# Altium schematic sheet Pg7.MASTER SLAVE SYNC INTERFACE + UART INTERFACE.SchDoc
size 431 x 279 mm; Date: Not shown in title block; ApprovedBy: Not shown in title block; CheckedBy: Not shown in title block; Author: Not shown in title block; CompanyName: Not shown in title block; Engineer: Not shown in title block; Organization: Not shown in title block; Address1: Not shown in title block; Address2: Not shown in title block; Address3: Not shown in title block; Address4: Not shown in title block; DocumentNumber: 7; Revision: Use project parameter SCH_Rev; SheetNumber: 7; SheetTotal: 8; PageSetup: Record=PageOptions|CenterHorizontal=True|CenterVertical=True|PrintScale=1.00|XCorrection=1.00|YCorrection=1.00|PrintKind=0|BorderSize=5000000|LeftOffset=0|BottomOffset=0|Orientation=2|PaperLength=1000|PaperWidth=1000|Scale=100|PaperSource=15|PrintQuality=600|MediaType=1|DitherType=10|PaperKind=Letter|PrintScaleMode=1
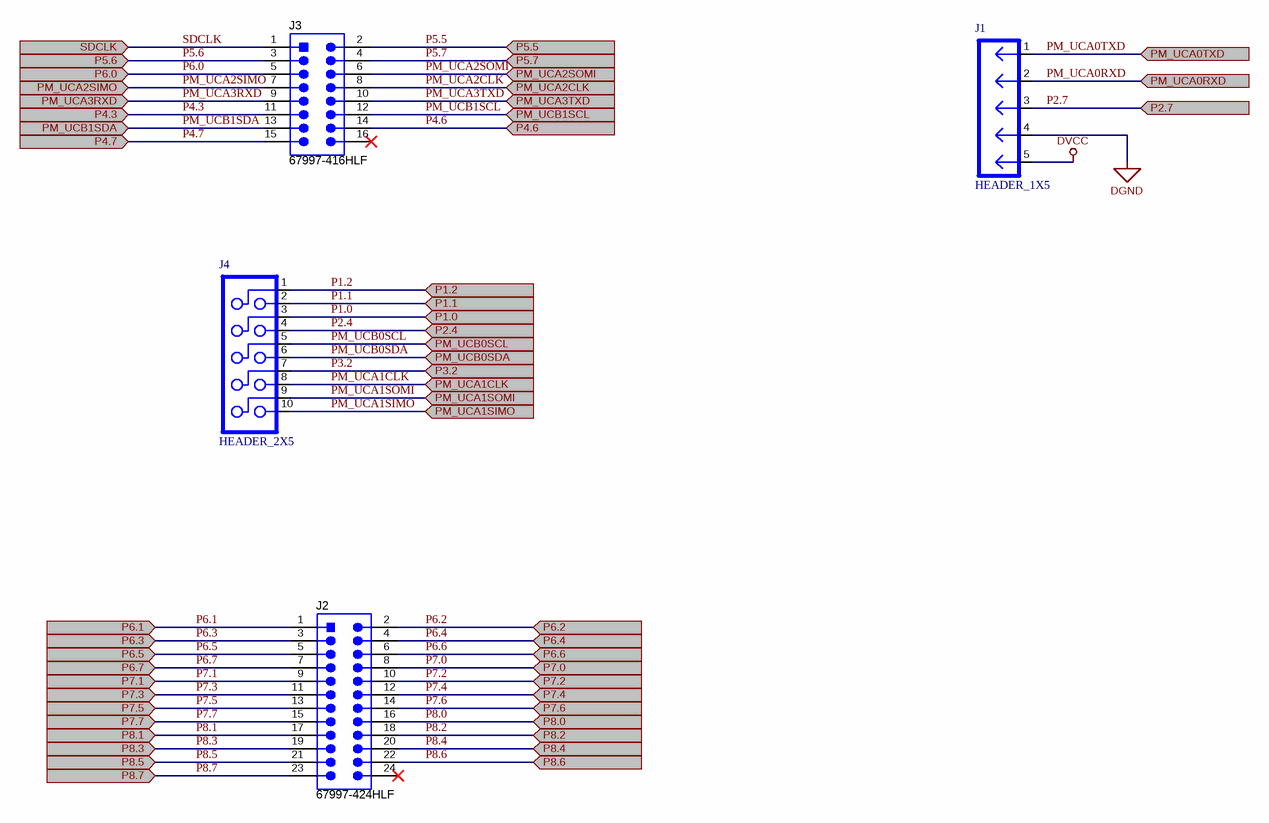
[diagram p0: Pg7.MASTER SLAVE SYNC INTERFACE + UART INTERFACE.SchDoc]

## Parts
J1  HEADER_1X5  [HEADER_5P]
J2  67997-424HLF  [TSW-112-07-G-D]
J3  67997-416HLF  [TSW-108-07-G-D]
J4  HEADER_2X5  [HDR2X5]

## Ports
P1.0, P1.1, P1.2, P2.4, P2.7, P3.2, P4.3, P4.6, P4.7, P5.5, P5.6, P5.7, P6.0, P6.1, P6.2, P6.3, P6.4, P6.5, P6.6, P6.7, P7.0, P7.1, P7.2, P7.3, P7.4, P7.5, P7.6, P7.7, P8.0, P8.1, P8.2, P8.3, P8.4, P8.5, P8.6, P8.7, PM_UCA0RXD, PM_UCA0TXD, PM_UCA1CLK, PM_UCA1SIMO, PM_UCA1SOMI, PM_UCA2CLK, PM_UCA2SIMO, PM_UCA2SOMI, PM_UCA3RXD, PM_UCA3TXD, PM_UCB0SCL, PM_UCB0SDA, PM_UCB1SCL, PM_UCB1SDA, SDCLK

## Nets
DGND: J1.4
DVCC: J1.5
P1.0: J4.3(P3) ; port P1.0
P1.1: J4.2(P2) ; port P1.1
P1.2: J4.1(P1) ; port P1.2
P2.4: J4.4(P4) ; port P2.4
P2.7: J1.3 ; port P2.7
P3.2: J4.7(P7) ; port P3.2
P4.3: J3.11 ; port P4.3
P4.6: J3.14 ; port P4.6
P4.7: J3.15 ; port P4.7
P5.5: J3.2 ; port P5.5
P5.6: J3.3 ; port P5.6
P5.7: J3.4 ; port P5.7
P6.0: J3.5 ; port P6.0
P6.1: J2.1 ; port P6.1
P6.2: J2.2 ; port P6.2
P6.3: J2.3 ; port P6.3
P6.4: J2.4 ; port P6.4
P6.5: J2.5 ; port P6.5
P6.6: J2.6 ; port P6.6
P6.7: J2.7 ; port P6.7
P7.0: J2.8 ; port P7.0
P7.1: J2.9 ; port P7.1
P7.2: J2.10 ; port P7.2
P7.3: J2.11 ; port P7.3
P7.4: J2.12 ; port P7.4
P7.5: J2.13 ; port P7.5
P7.6: J2.14 ; port P7.6
P7.7: J2.15 ; port P7.7
P8.0: J2.16 ; port P8.0
P8.1: J2.17 ; port P8.1
P8.2: J2.18 ; port P8.2
P8.3: J2.19 ; port P8.3
P8.4: J2.20 ; port P8.4
P8.5: J2.21 ; port P8.5
P8.6: J2.22 ; port P8.6
P8.7: J2.23 ; port P8.7
PM_UCA0RXD: J1.2 ; port PM_UCA0RXD
PM_UCA0TXD: J1.1 ; port PM_UCA0TXD
PM_UCA1CLK: J4.8(P8) ; port PM_UCA1CLK
PM_UCA1SIMO: J4.10(P10) ; port PM_UCA1SIMO
PM_UCA1SOMI: J4.9(P9) ; port PM_UCA1SOMI
PM_UCA2CLK: J3.8 ; port PM_UCA2CLK
PM_UCA2SIMO: J3.7 ; port PM_UCA2SIMO
PM_UCA2SOMI: J3.6 ; port PM_UCA2SOMI
PM_UCA3RXD: J3.9 ; port PM_UCA3RXD
PM_UCA3TXD: J3.10 ; port PM_UCA3TXD
PM_UCB0SCL: J4.5(P5) ; port PM_UCB0SCL
PM_UCB0SDA: J4.6(P6) ; port PM_UCB0SDA
PM_UCB1SCL: J3.12 ; port PM_UCB1SCL
PM_UCB1SDA: J3.13 ; port PM_UCB1SDA
SDCLK: J3.1 ; port SDCLK

Not connected (* = marked no-connect by the designer): J2 24*; J3 16*

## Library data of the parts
J1 = HEADER_1X5: Header, Male 5-pin, 100mil spacing,; Manufacturer: TE Connectivity; PartNumber: 826926-5; area: 55000; Value: PEC05SAAN
J2 = TSW-112-07-G-D: Header, TH, 100mil, 12x2, Gold plated, 230 mil above insulator; Manufacturer: FCI; SymbolCreator: a0412235; U/M: EA
J3 = PBC08DBAN: Header, 8x2, 100mil, TH; Manufacturer: FCI; SymbolCreator: a0412235; U/M: EA
J4 = HEADER_2X5: Header, Male 2x5-pin, 100mil spacing; Manufacturer: FCI; PartNumber: 67997-410HLF; area: 100000; Value: PEC05DAAN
